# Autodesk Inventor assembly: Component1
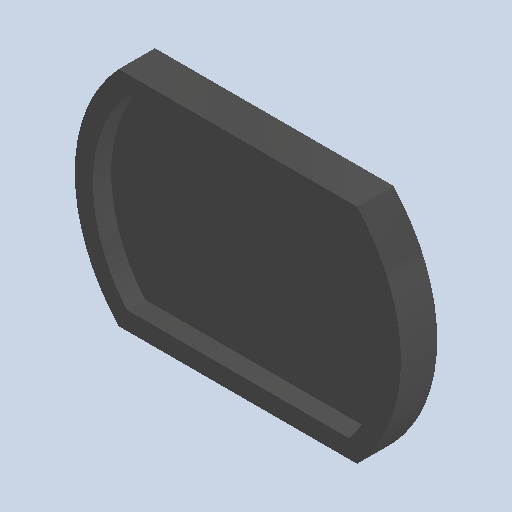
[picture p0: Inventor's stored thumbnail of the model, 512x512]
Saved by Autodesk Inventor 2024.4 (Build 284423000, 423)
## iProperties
Created: 2025-04
Part Number: Component1
Document SubType Name: Assembly
Designer: AdminForWorker
Title: Component1
Author: AdminForWorker
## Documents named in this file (3)
- c:\worker\convert-fusion-r02-cosv3\tmp\job-1\12\temp\files\1718eded-1d8f-43a0-9465-10b5a2cd5079\Component1.iam
- c:\worker\convert-fusion-r02-cosv3\tmp\job-1\12\temp\files\1718eded-1d8f-43a0-9465-10b5a2cd5079\Component2.ipt
- c:\worker\convert-fusion-r02-cosv3\tmp\job-1\12\temp\files\1718eded-1d8f-43a0-9465-10b5a2cd5079\Part6.ipt
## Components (2 placed, 2 different names)
1. Component2:1
2. Part6
